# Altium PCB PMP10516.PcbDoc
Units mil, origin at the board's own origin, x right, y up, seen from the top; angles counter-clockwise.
Board outline 2300 x 2845 mil, 4 copper layers (Top Layer, MidLayer1, MidLayer2, Bottom Layer), stack 88.6 mil thick; 62 components, 21 nets, 113 pads, 13 vias.
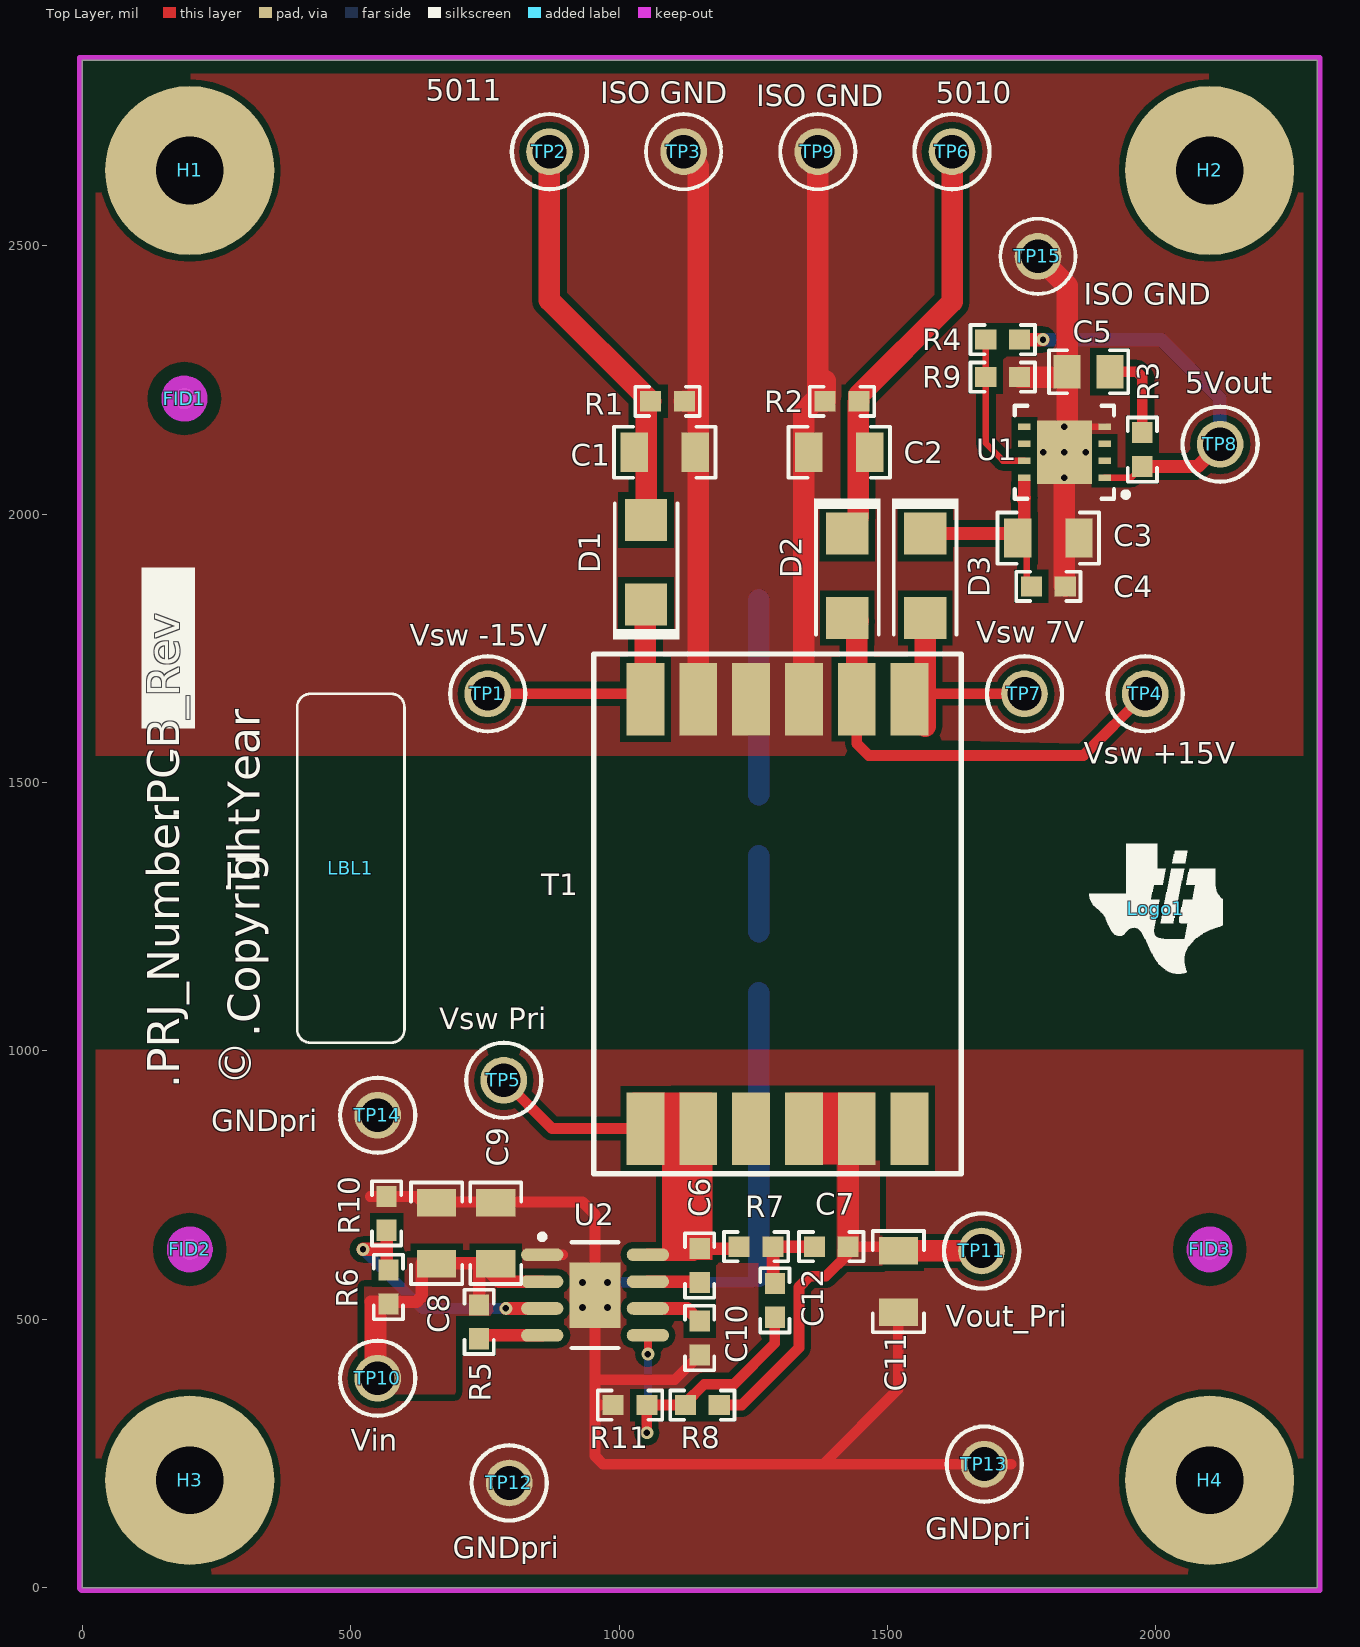
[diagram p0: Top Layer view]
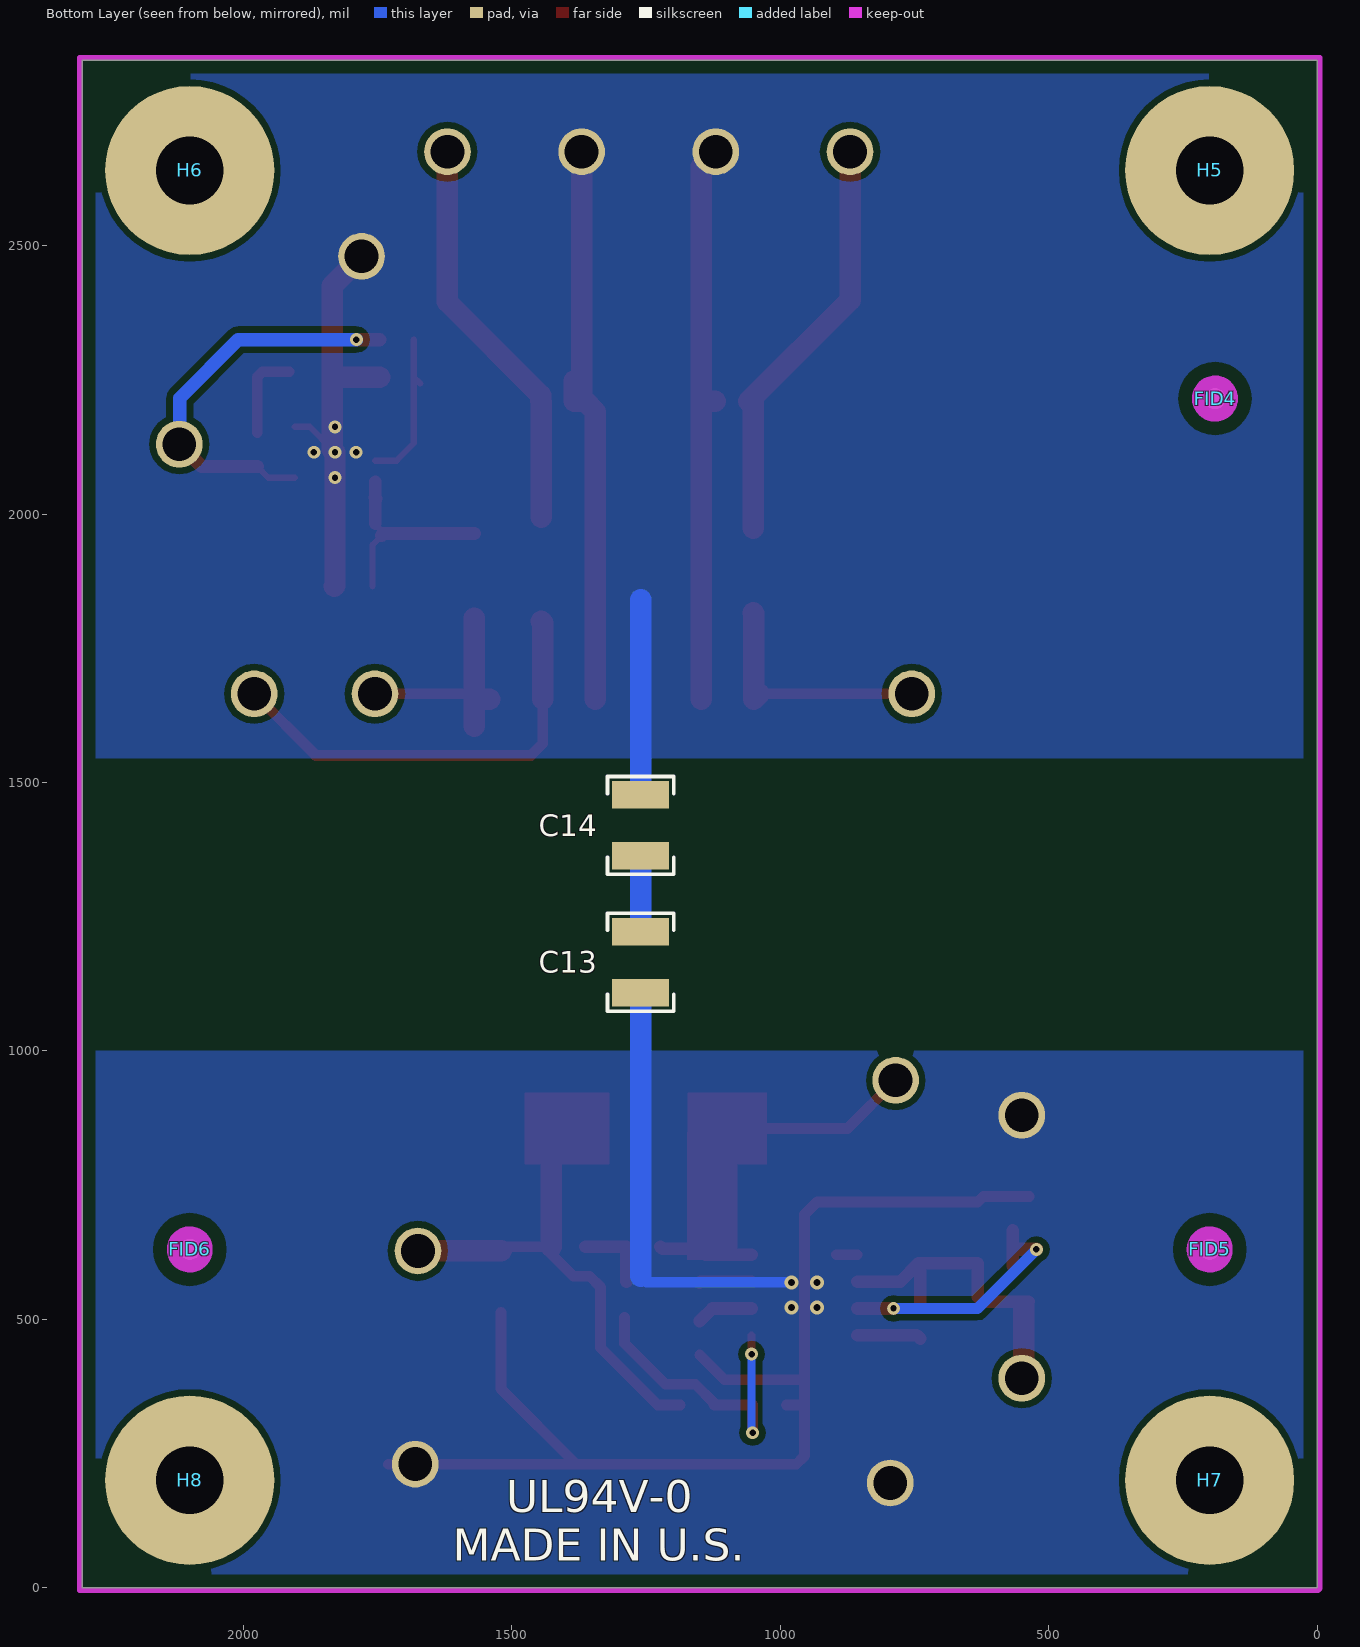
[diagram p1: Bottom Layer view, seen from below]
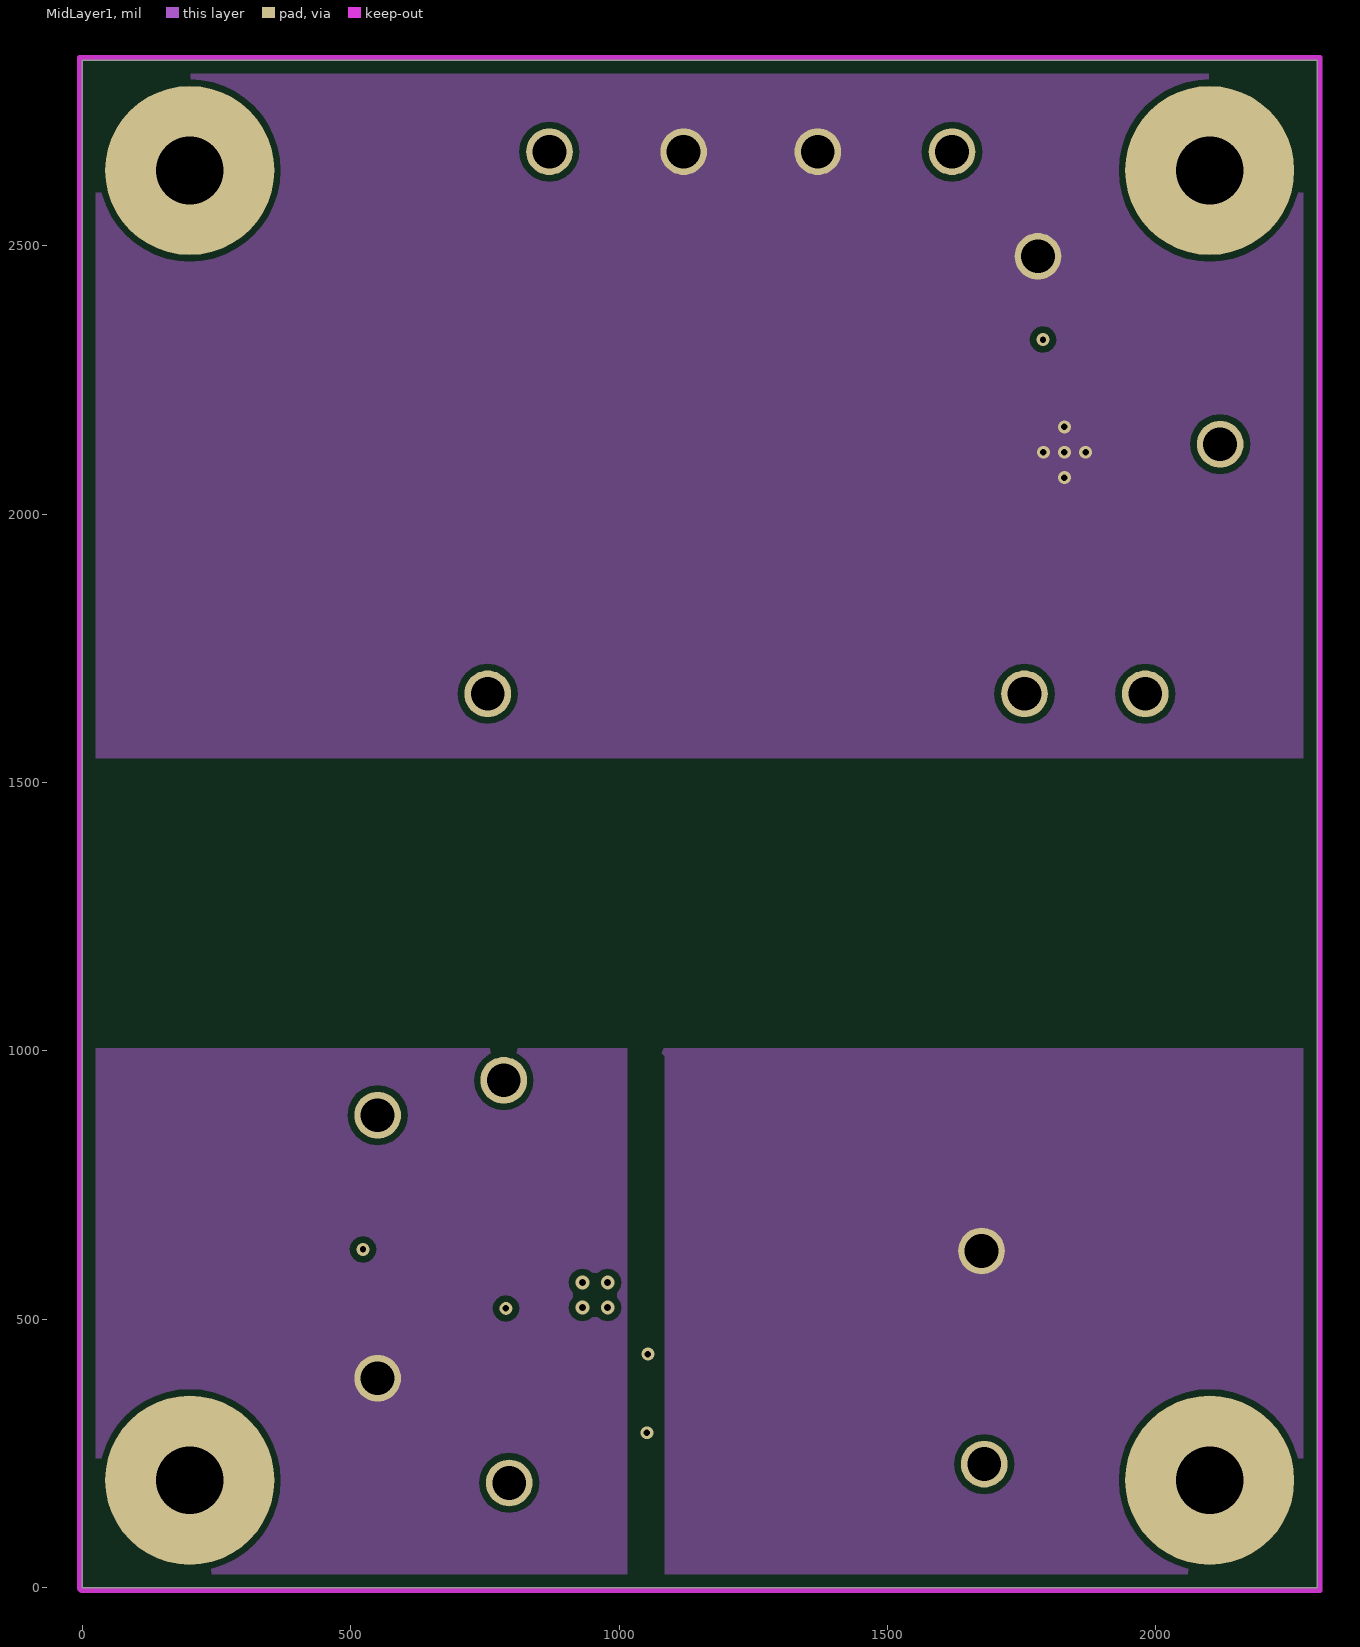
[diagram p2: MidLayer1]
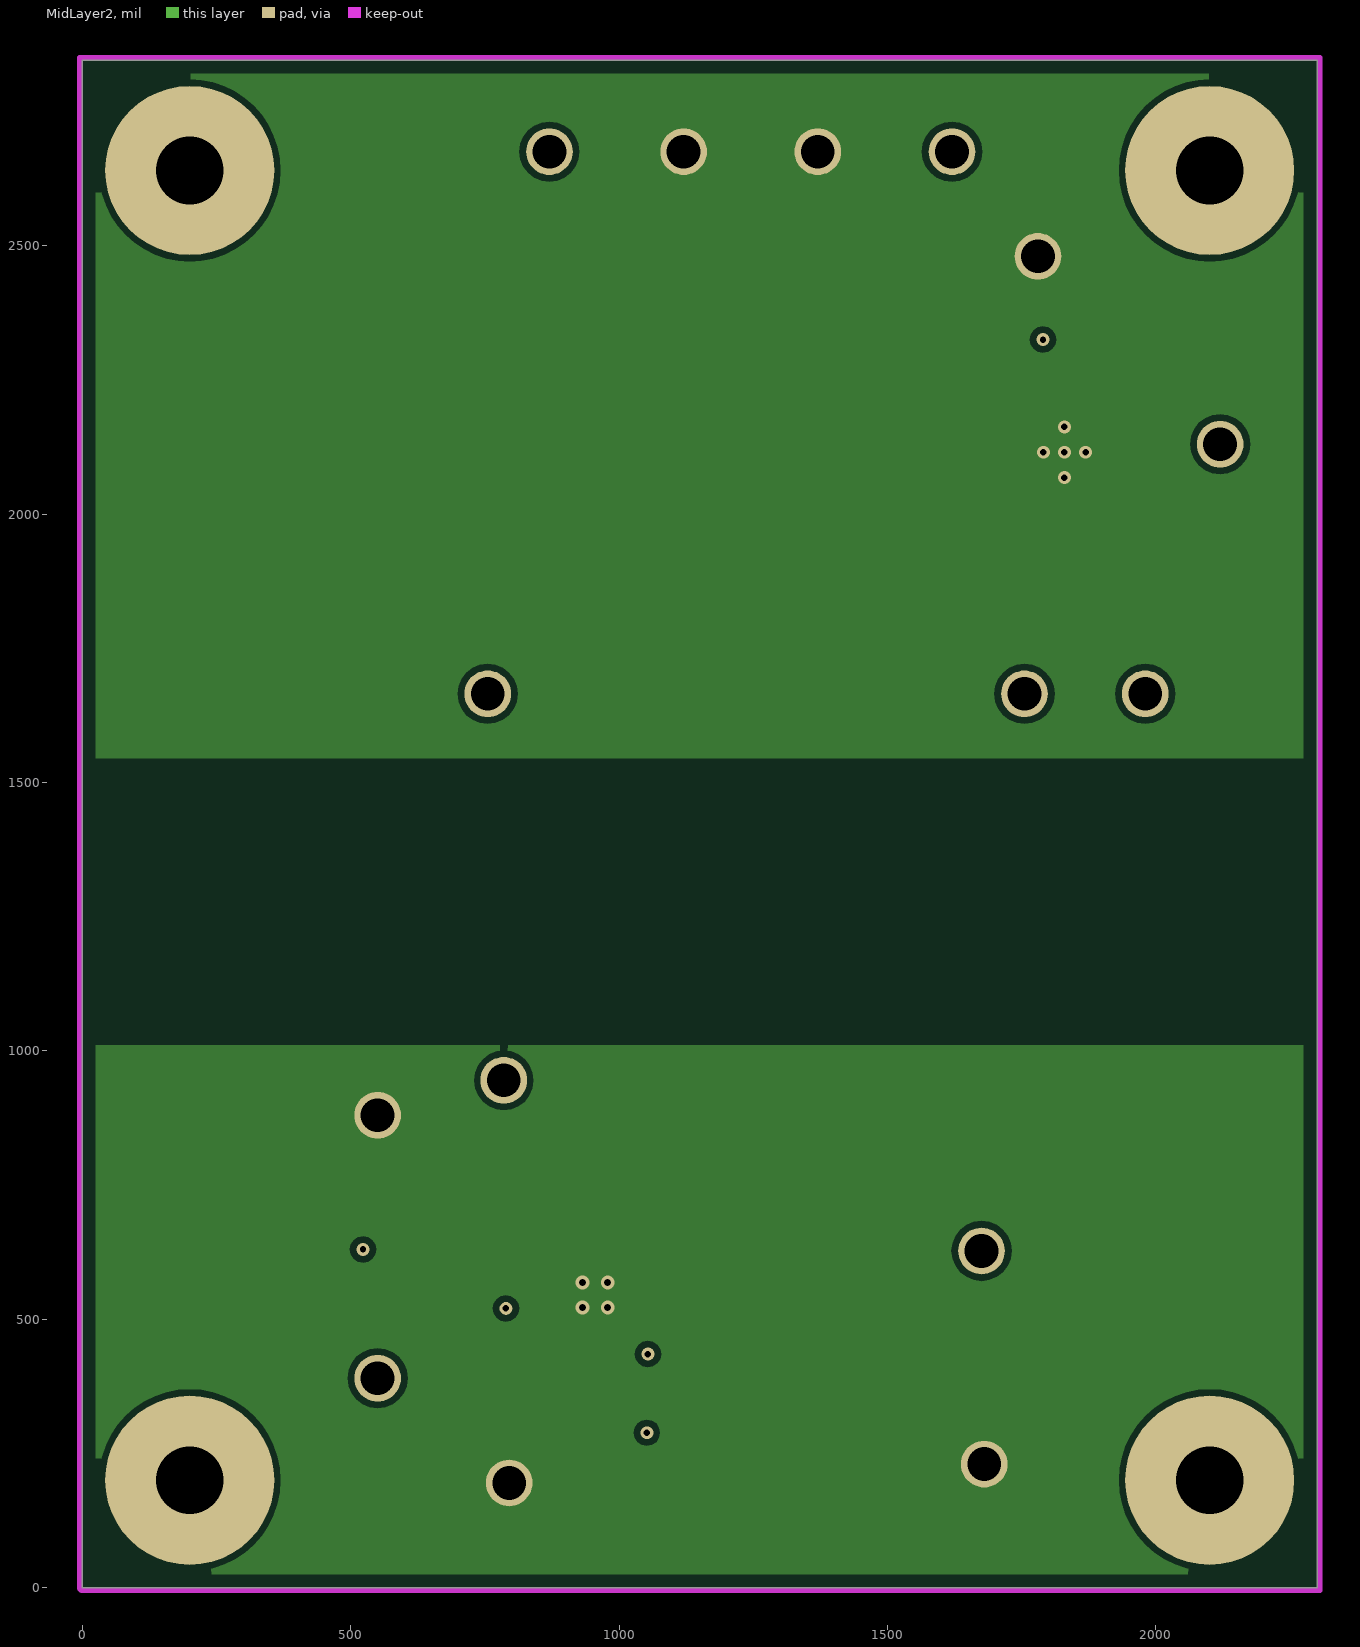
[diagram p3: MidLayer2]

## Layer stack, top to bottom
Top Solder: solder mask 0.4, Solder Resist, Dk 3.5
Top Layer: signal copper 1.4
Dielectric1: core 59.2, FR-4, Dk 4.8
MidLayer1: signal copper 0.7
Dielectric2: prepreg 12.6, FR-4, Dk 4.8
MidLayer2: signal copper 0.7
Dielectric3: core 12.6, FR-4, Dk 4.8
Bottom Layer: signal copper 1.4
Bottom Solder: solder mask 0.4, Solder Resist, Dk 3.5

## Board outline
0,0 0,2845 2300,2845 2300,0

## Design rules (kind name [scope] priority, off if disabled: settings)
AcuteAngle [All] p1: minimum=4.50000000000000E+0001 checktracksonly=FALSE
AssemblyTestPointUsage [All] p1: valid=2
Clearance Clearance_BoardEdge_MountingHoles [OnCopper and InComponentClass('Mounting Holes') vs IsKeepOut] p1: gap=40
Clearance Clearance_BoardEdge_Poly [OnCopper and InPoly vs IsKeepOut] p2: gap=25
Clearance Clearance_BoardEdge [OnCopper and Not InComponentClass('Logo') and not InComponentClass('FiducialMark') and not InRegion(1000,500,4000,800) and Not IsKeepout vs IsKeepOut] p3: gap=75
Clearance Clearance_Poly [InPolygon] p4: gap=12
Clearance [All] p5: gap=10
ComponentClearance ComponentClearance_Shunt [InComponentClass('Header') vs InComponentClass('Shunt')] p1: gap=0 collisioncheckmode=3 verticalgap=0 showdistances=FALSE
ComponentClearance ComponentClearance_Logo [InComponentClass('Logo')] p2: gap=50 collisioncheckmode=3 verticalgap=10 showdistances=FALSE
ComponentClearance ComponentClearance_ScrewToNut [(HasFootprint('NY PMS 440 0025 PH')) vs (HasFootprint('Keystone_1902C'))] p3: gap=5 collisioncheckmode=3 verticalgap=10 showdistances=FALSE
ComponentClearance ComponentClearance_MountingHoles [InComponentClass('Mounting Holes')] p4: gap=250 collisioncheckmode=3 verticalgap=100000 showdistances=FALSE
ComponentClearance ComponentClearance_SmallPassives [HasFootprint('0201*') or HasFootprint('0402*') or HasFootprint('0508') or HasFootprint('0603*') or HasFootprint('0612') or HasFootprint('0805*') or HasFootprint('0815*') or HasFootprint('0830*') or HasFootprint('1206*') or HasFootprint('1210*') or HasFootprint('1808*') or HasFootprint('1812*') or HasFootprint('1825*') or HasFootprint('2010*') or HasFootprint('2220*') or HasFootprint('2225*') or HasFootprint('2512*') or HasFootprint('2728*') or HasFootprint('3518*') vs HasFootprint('0201*') or HasFootprint('0402*') or HasFootprint('0508') or HasFootprint('0603*') or HasFootprint('0612') or HasFootprint('0805*') or HasFootprint('0815*') or HasFootprint('0830*') or HasFootprint('1206*') or HasFootprint('1210*') or HasFootprint('1808*') or HasFootprint('1812*') or HasFootprint('1825*') or HasFootprint('2010*') or HasFootprint('2220*') or HasFootprint('2225*') or HasFootprint('2512*') or HasFootprint('2728*') or HasFootprint('3518*')] p5: gap=20 collisioncheckmode=3 verticalgap=10 showdistances=FALSE
ComponentClearance ComponentClearance_THtoSMT [IsThruComponent vs IsSMTComponent] p6: gap=50 collisioncheckmode=3 verticalgap=30 showdistances=FALSE
ComponentClearance ComponentClearance_THtoTH [IsThruComponent vs IsThruComponent] p7: gap=118.11 collisioncheckmode=3 verticalgap=30 showdistances=FALSE
ComponentClearance [All] p8: gap=40 collisioncheckmode=3 verticalgap=10 showdistances=FALSE
DiffPairsRouting [All] p1: maxlimit=100 minlimit=10 mostfreqgap=10 toplayer_minwidth=15 toplayer_maxwidth=15 toplayer_prefwidth=15 midlayer1_minwidth=15 midlayer1_maxwidth=15 midlayer1_prefwidth=15 midlayer2_minwidth=15 midlayer2_maxwidth=15 midlayer2_prefwidth=15 bottomlayer_minwidth=15 bottomlayer_maxwidth=15 bottomlayer_prefwidth=15 maxuncoupledlength=1000
FabricationTestPointUsage TestPointUsage [All] p1: valid=2 allowmultiple=FALSE
FabricationTestpoint Testpoint [All] p1: side=3 testpointundercomponent=TRUE minsize=40 maxsize=100 preferedsize=60 minholesize=0 maxholesize=40 preferedholesize=32 testpointgrid=1 allowsidetop=TRUE allowsidebottom=TRUE usegrid=TRUE gridtolerance=0.01
FanoutControl Fanout_LCC [IsLCC] p1: bgadir=Out bgaviamode=Centered fanoutstyle=Auto fanoutdirection=Alternating viagrid=1 // Fanout_LCC (Default Rule)
FanoutControl Fanout_BGA [IsBGA] p2: bgadir=Out bgaviamode=Centered fanoutstyle=Auto fanoutdirection=Alternating viagrid=1 // Fanout_BGA (Default Rule)
FanoutControl Fanout_Default [All] p4: bgadir=Out bgaviamode=Centered fanoutstyle=Auto fanoutdirection=Alternating viagrid=1 // Fanout_Default (Default Rule)
FanoutControl Fanout_Small [(CompPinCount < 5)] p5: bgadir=Out bgaviamode=Centered fanoutstyle=Auto fanoutdirection=OutThenIn viagrid=1 // Fanout_Small (Default Rule)
HoleSize [All] p1: absolutevalues=TRUE maxlimit=251 minlimit=10 maxpercent=80.000 minpercent=20.000
MinimumAnnularRing MinimumAnnularRing_ThermalPadVias [IsVia and InAnyComponent] p1: minimumring=6
MinimumAnnularRing [All] p2: minimumring=6
MinimumSolderMaskSliver MinimumSolderMaskSliver_Logo [InComponentClass('Logo') vs InComponentClass('Logo')] p1: minsoldermaskwidth=0.7
MinimumSolderMaskSliver [All] p2: minsoldermaskwidth=3.94
PlaneConnect [All] p1: planeconnectstyle=Relief reliefexpansion=10 reliefentries=4 reliefconductorwidth=10 reliefairgap=10
PolygonConnect [All] p1: connectstyle=Direct reliefconductorwidth=10 reliefentries=4 polygonreliefangle="90 Angle" airgapwidth=10
RoutingVias ThermalPadVias [IsVia and InAnyComponent] p1: holewidth=12 width=24 viastyle="Through Hole" minholewidth=10 minwidth=22 maxholewidth=15 maxwidth=30
RoutingVias [All] p2: holewidth=16 width=34 viastyle="Through Hole" minholewidth=10 minwidth=22 maxholewidth=40 maxwidth=65
SMDToCorner [All] p1: distance=30000
SilkToSilkClearance [All] p1: silktosilkclearance=5
SilkToSolderMaskClearance SilkscreenOverComponentPads [IsPad] p1: minsilkscreentomaskgap=5 clearancetoexposedcopper=TRUE
SolderMaskExpansion [All] p1: expansion=1.97
UnpouredPolygon [All] p1: allowunpoured=FALSE
Width [All] p1: maxlimit=100 minlimit=6 preferedwidth=10 checkconnectedcopper=TRUE
15 further rules are at their usual default settings.

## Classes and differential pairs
component class PMP10516_Rev2: C1 C2 C3 C4 C5 C6 C7 C8 C9 C10 C11 C12 C13 C14 D1 D2 D3 R1 R2 R3 R4 R5 R6 R7 R8 R9 R10 R11 T1 TP1 TP2 TP3 TP4 TP5 TP6 TP7 TP8 TP9 TP10 TP11 TP12 TP13 TP14 TP15 U1 U2
component class Label: LBL1
component class FiducialMark: FID1 FID2 FID3 FID4 FID5 FID6
component class PMP10516_Hardware_ANSI-B: FID1 FID2 FID3 FID4 FID5 FID6 H1 H2 H3 H4 H5 H6 H7 H8 LBL1 Logo1
component class Logo: Logo1
component class "Mounting Holes": H1 H2 H3 H4

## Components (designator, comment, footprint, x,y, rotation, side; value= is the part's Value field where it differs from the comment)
C1 "GRM31CR71E106KA12L" 1206 1085,2115 r180 top
C2 "GRM31CR71E106KA12L" 1206 1410,2115 r180 top
C3 "GRM31CR71E106KA12L" 1206 1799.45,1955 r0 top
C4 "06033C104JAT2A" 0603 1799.45,1865 r0 top
C5 "C0805C225K8RACTU" 0805_HV 1874.45,2265 r180 top
C6 "06035C104KAT2A" 0603 1150,600 r270 top
C7 "C0603C223K5RACTU" 0603 1395,635 r180 top
C8 "GRM31CR71H225KA88L" 1206 660,660 r90 top
C9 "GRM31CR71H225KA88L" 1206 770,660 r90 top
C10 "GRM188R71E105KA12D" 0603 1150,465 r270 top
C11 "GRM31CR71E106KA12L" 1206 1520,570 r270 top
C12 "C0603C102J5GAC" 0603 1290,535 r270 top
C13 "VJ1210A222JXGAT5Z" 1210 1260,1165 r270 bottom
C14 "VJ1210A222JXGAT5Z" 1210 1260,1420 r270 bottom
D1 "ES1D-13-F" SMA 1050,1910 r90 top
D2 "ES1D-13-F" SMA 1425,1885 r270 top
D3 "ES1D-13-F" SMA 1570,1885 r270 top
FID1 "Fiducial" Fiducial10-20#1 190,2215 r0 top
FID2 "Fiducial" Fiducial10-20#1 200,630 r0 top
FID3 "Fiducial" Fiducial10-20#1 2100,630 r0 top
FID4 "Fiducial" Fiducial10-20#2 190,2215 r180 bottom
FID5 "Fiducial" Fiducial10-20#2 200,630 r180 bottom
FID6 "Fiducial" Fiducial10-20#2 2100,630 r180 bottom
H1 "NY PMS 440 0025 PH" "NY PMS 440 0025 PH" 200,2640 r0 top locked
H2 "NY PMS 440 0025 PH" "NY PMS 440 0025 PH" 2100,2640 r0 top locked
H3 "NY PMS 440 0025 PH" "NY PMS 440 0025 PH" 200,200 r0 top locked
H4 "NY PMS 440 0025 PH" "NY PMS 440 0025 PH" 2100,200 r0 top locked
H5 "1902C" Keystone_1902C 200,2640 r180 bottom locked
H6 "1902C" Keystone_1902C 2100,2640 r180 bottom locked
H7 "1902C" Keystone_1902C 200,200 r180 bottom locked
H8 "1902C" Keystone_1902C 2100,200 r180 bottom locked
LBL1 "Size: 0.65\" x 0.20 \"" Label_650x200 500,1340 r90 top
Logo1 "Texas Instruments" TI_Symbol_Overlay_Medium 2000,1265 r0 top
R1 "Used in BOM report" 0603 1090,2210 r0 top
R2 "Used in BOM report" 0603 1415,2210 r0 top
R3 "CRCW06030000Z0EA" 0603 1974.45,2120 r270 top
R4 "CRCW060331K6FKEA" 0603 1714.45,2325 r0 top
R5 "CRCW0603365KFKEA" 0603 739,495 r270 top
R6 "CRCW0603100KFKEA" 0603 570,560 r270 top
R7 "CRCW060310K0FKEA" 0603 1255,635 r0 top
R8 "CRCW0603143KFKEA" 0603 1155,340 r0 top
R9 "CRCW060310K0FKEA" 0603 1714.45,2255 r180 top
R10 "CRCW06036K98FKEA" 0603 566.7,697.19 r270 top
R11 "CRCW060320K0FKEA" 0603 1020,340 r0 top
T1 "RA7157-AL" RA7157-AL 1295,1255 r90 top
TP1 "Vsw -15V" Keystone5012 755,1665 r0 top
TP2 "5011" Keystone5011 870,2675 r0 top
TP3 "ISO GND" Keystone5126 1120,2675 r0 top
TP4 "Vsw +15V" Keystone5012 1980,1665 r0 top
TP5 "Vsw Pri" Keystone5012 785,945 r0 top
TP6 "5010" Keystone5010 1620,2675 r0 top
TP7 "Vsw 7V" Keystone5012 1755,1665 r0 top
TP8 "5Vout" Keystone5010 2119.45,2130 r0 top
TP9 "ISO GND" Keystone5126 1370,2675 r180 top
TP10 "Vin" Keystone5010 550,390 r0 top
TP11 "Vout_Pri" Keystone5010 1675,627.09 r0 top
TP12 "GNDpri" Keystone5011 795,195 r0 top
TP13 "GNDpri" Keystone5011 1680,230 r0 top
TP14 "GNDpri" Keystone5011 550,880 r0 top
TP15 "ISO GND" Keystone5126 1780,2480 r0 top
U1 "LP2951CSD" SDC08A 1829.45,2115 r180 top
U2 "LM5017MRE/NOPB" DDA0008B_N 955,545 r0 top

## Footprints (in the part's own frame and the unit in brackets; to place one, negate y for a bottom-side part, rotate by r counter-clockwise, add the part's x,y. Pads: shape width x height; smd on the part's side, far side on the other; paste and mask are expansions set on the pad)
0603 [mm] "0603 from SM-752 data"
  rect 1x0.95 smd: 1(-0.8,0) 2(0.8,0)
  silkscreen extent -1.52,-0.69 1.52,0.69, body extent -0.87,-0.47 0.87,0.47, height 0.85
0805_HV [mil] "0805 with 30mil clearance between pads"
  rect 50x63 smd: 1(-40,0) 2(40,0)
  silkscreen extent -74,-40 74,40, body extent -43,-29 43,29, height 43
1206 [mm] "1206 from SM-752 data"
  rect 1.3x1.85 smd: 1(-1.45,0) 2(1.45,0)
  silkscreen extent -2.4,-1.21 2.4,1.21, body extent -1.7,-0.9 1.7,0.9, height 1.35
1210 [mm] "1210 from SM-752 data"
  rect 1.3x2.7 smd: 1(-1.45,0) 2(1.45,0)
  silkscreen extent -2.32,-1.57 2.32,1.57, body extent -1.7,-1.35 1.7,1.35, height 1.35
DDA0008B_N [mm] "SOIC, 8-Leads, Body 4.9x3.9mm, Pitch 1.27mm, Exposed Pad, IPC Medium Density"
  oval 2x0.6 smd: 1(-2.5,1.905) 2(-2.5,0.635) 3(-2.5,-0.635) 4(-2.5,-1.905) 5(2.5,-1.905) 6(2.5,-0.635) 7(2.5,0.635) 8(2.5,1.905)
  rect 2.41x3.1 smd: 9(0,0)
  silkscreen extent -2.62,-2.5 1.1,2.88, body extent -2,-2.5 2,2.5, height 1.68
Fiducial10-20#1 [mm]
  round 1 smd paste-0.5 mask+0.5: 1(0,0)
  Top Layer keep-out circle w1.178: c0,0 r0.5
Fiducial10-20#2 [mm]
  round 1 smd mask+0.5: 1(0,0)
  Top Layer keep-out circle w1.178: c0,0 r0.5
Keystone5010 [mil] "Keystone Multipurpose loops"
  round 87 hole 63: 1(0,0)
  silkscreen extent -70,-70 70,70, body extent -63,-63 63,62, height 319
Keystone5011 [mil] "Keystone Multipurpose loops"
  round 87 hole 63: 1(0,0)
  silkscreen extent -70,-70 70,70, body extent -63,-63 63,62, height 319
Keystone5012 [mil] "Keystone Multipurpose loops"
  round 87 hole 63: 1(0,0)
  silkscreen extent -70,-70 70,70, body extent -63,-63 63,62, height 319
Keystone5126 [mil] "Keystone Multipurpose loops"
  round 87 hole 63: 1(0,0)
  silkscreen extent -70,-70 70,70, body extent -63,-63 63,62, height 319
Keystone_1902C [mil] "Hex Standoff, 4-40 threaded, nylon"
  body extent -145,-126 146,126, height 501
Label_650x200 [mil] "Thermal Transfer Label"
  silkscreen extent -325,-100 325,100, body extent -326,-101 326,101, height 1
"NY PMS 440 0025 PH" [mm] "4-40 nylon screw and mounting hole"
  round 8 hole 3.2: 1(0,0)
  body extent -3.3,-3.3 3.3,3.3, height 2.69
RA7157-AL [mm] "COILCRAFT RA7157-AL CUSTOM TRANSFORMER"
  round 1.524 on Top Overlay: 0(-6.9,6.2)
  rect 3.43x1.79 smd: 1(-10.155,6.25) 2(-10.155,3.75) 3(-10.155,1.25) 4(-10.155,-1.25) 5(-10.155,-3.75) 6(-10.155,-6.25) 7(10.155,-6.25) 8(10.155,-3.75) 9(10.155,-1.25) 10(10.155,1.25) 11(10.155,3.75) 12(10.155,6.25)
  silkscreen extent -12.3,-8.7 12.3,8.7, body extent -12.3,-8.7 12.3,8.7, height 8.65
SDC08A [mm] "SON, 8-Leads, Body 4x4mm, Pitch 0.8mm, NSC Recommended"
  rect 0.6x0.3 smd paste-0.15 mask+0.051: 1(-1.9,1.2) 2(-1.9,0.4) 3(-1.9,-0.4) 4(-1.9,-1.2) 5(1.9,-1.2) 6(1.9,-0.4) 7(1.9,0.4) 8(1.9,1.2)
  rect 2.6x3 smd paste-1.5 mask+0.051: 9(0,0)
  silkscreen extent -3.03,-2.2 2.35,2.2, body extent -2.05,-2.05 2.05,2.05, height 0.8
SMA [mm] "Molded Diode, 2-Leads, Body 4.3x2.6mm, IPC Medium Density, based on OnSemi component dimensions and land pattern"
  rect 2x2 smd: 1(-2,0) 2(2,0)
  silkscreen extent -3.66,-1.57 2.79,1.57, body extent -2.6,-1.3 2.6,1.3, height 2.42
TI_Symbol_Overlay_Medium [mil]
  silkscreen extent -124,-122 124,120

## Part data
C1 C2 C3 C11: "CAP, CERM, 10uF, 25V, +/-10%, X7R, 1206"
C4: "CAP, CERM, 0.1uF, 25V, +/-5%, X7R, 0603"
C5: "CAP, CERM, 2.2uF, 10V, +/-10%, X7R, 0805"
C6: "CAP, CERM, 0.1uF, 50V, +/-10%, X7R, 0603"
C7: "CAP, CERM, 0.022uF, 50V, +/-10%, X7R, 0603"
C8 C9: "CAP, CERM, 2.2uF, 50V, +/-10%, X7R, 1206"
C10: "CAP, CERM, 1uF, 25V, +/-10%, X7R, 0603"
C12: "CAP, CERM, 1000pF, 50V, +/-5%, C0G/NP0, 0603"
C13 C14: "CAP, CERM, 2200 pF, 1000 V, +/- 5%, C0G/NP0, 1210"
D1 D2 D3: "Diode, Ultrafast, 200V, 1A, SMA"
FID1 FID2 FID3 FID4 FID5 FID6: "Fiducial mark.  There is nothing to buy or mount."
H1 H2 H3 H4: "Machine Screw, Round, #4-40 x 1/4, Nylon, Philips panhead"
H5 H6 H7 H8: "Standoff, Hex, 0.5\"L #4-40 Nylon"
LBL1: library part THT-14-423-10, "Thermal Transfer Printable Labels, 0.650\" W x 0.200\" H - 10,000 per roll"
Logo1: library part TI_Logo, "Texas Instrument Corporate Signature"
R1 R2: library part Resistor, "RES, xxx ohm, x%, xW, [PackageReference]"
R3: "RES, 0 ohm, 5%, 0.1W, 0603"
R4: "RES, 31.6k ohm, 1%, 0.1W, 0603"
R5: "RES, 365k ohm, 1%, 0.1W, 0603"
R6: "RES, 100k ohm, 1%, 0.1W, 0603"
R7 R9: "RES, 10.0k ohm, 1%, 0.1W, 0603"
R8: "RES, 143k ohm, 1%, 0.1W, 0603"
R10: "RES, 6.98k ohm, 1%, 0.1W, 0603"
R11: "RES, 20.0k ohm, 1%, 0.1W, 0603"
T1: library part RA7157-AL_V2, "1:1.5:1.5:0.7 Turns Ratio Transformer"
TP1 TP4 TP5 TP7: library part 5012, "Test Point, Multipurpose, White, TH"
TP2: "Test Point, Multipurpose, Black, TH"
TP3 TP9 TP15: library part 5126, "Test Point, Multipurpose, Green, TH"
TP6: "Test Point, Multipurpose, Red, TH"
TP8 TP10 TP11: library part 5010, "Test Point, Multipurpose, Red, TH"
TP12 TP13 TP14: library part 5011, "Test Point, Multipurpose, Black, TH"
U1: "Series of Adjustable Micropower Voltage Regulators, 8-pin LLP"
U2: "100V, 600mA Constant On-Time Synchronous Buck Regulator, DDA0008B"

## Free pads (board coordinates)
  round 24 hole 12: 0(789,520)

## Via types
v1: diameter 24, hole 12, Top Layer to Bottom Layer, 9 vias
v2: diameter 25.98, hole 12.99, Top Layer to Bottom Layer, tented top, 4 vias

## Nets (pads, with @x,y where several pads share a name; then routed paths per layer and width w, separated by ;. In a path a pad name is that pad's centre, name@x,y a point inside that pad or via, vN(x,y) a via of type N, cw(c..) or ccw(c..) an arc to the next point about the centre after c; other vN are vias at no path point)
5VOUT: R3.2 R4.2 TP8.1 U1.1 | length 745
  Top Layer w11.81: U1.1 1953.7,2067.76 R3.2
  Top Layer w25: R4.2 v1(1789.45,2325) ; R3.2 2077.95,2088.5 TP8.1
  Bottom Layer w25: v1(1789.45,2325) 2009.45,2325 2118.94,2215.51 TP8.1@2118.94,2129.87
"7V SW": D3.2 T1.7 TP7.1 | length 405
  Top Layer w20: 1580.2,1665 TP7.1
  Top Layer w40: T1.7 T1.7@1570,1654.8 ; T1.7@1570,1605 T1.7@1570,1654.8 ; D3.2 T1.7@1570,1654.8
"+15V SW": D2.2 T1.8 TP4.1 | length 822.9
  Top Layer w20: T1.8 1442.64,1572.36 1465,1550 1865,1550 TP4.1
  Top Layer w40: T1.8 1442.64,1797.64 D2.2@1445,1800
+15VOUT: C2.1 D2.1 R2.2 TP6.1 | length 753.7
  Top Layer w40: D2.1@1445,1993.74 1445,2208.5 R2.2 1446.5,2221.5 1620,2395 TP6.1
"-15V SW": D1.1 T1.12 TP1.1 | length 460.1
  Top Layer w20: TP1.1 T1.12@1038.74,1665
  Top Layer w40: T1.12@1038.74,1665 T1.12 1048.94,1815.2 D1.1@1050,1816.26
-15VOUT: C1.2 D1.2 R1.1 TP2.1 | length 786.4
  Top Layer w40: TP2.1 870,2398.5 R1.1 R1.1@1050,2201.5 ; D1.2@1050,1973.74 D1.2 R1.1@1050,2201.5 ; R1.1@1050,2205 R1.1@1050,2201.5
BST: C6.2 U2.7 | length 97.2
  Top Layer w23.62: U2.7 1148.5,570 C6.2
FB: C12.2 R8.1 R11.2 U2.5 | length 570.6
  Top Layer w15: v1(1053.43,435) U2.5
  Top Layer w20: v1(1051.5,288.5) R11.2 R8.1 1123.5,343.68 1158.53,378.7 1213.7,378.7 1290,455 C12.2
  Bottom Layer w15: v1(1051.5,288.5) 1053.42,290.43 v1(1053.43,435)
GND: C8.2 C9.2 C10.2 C11.2 C13.2 R10.1 R11.1 TP12.1 TP13.1 TP14.1 U2.1 U2.9 | length 3100.1
  Top Layer w20: 536,728.5 621.83,728.5 632,718.33 931.67,718.33 955,695 U2.9@955,565 ; U2.1 U2.1@895,620 ; U2.9@955,560 U2.9 955,387.19 ; R11.1 955,340 ; C10.2 1103.68,387.19 955,387.19 ; C11.2 1520,370 1380,230 ; 1730,230 TP13.1 1380,230 ; 955,340 955,387.19 ; 955,340 955,245 970,230 1380,230
  Bottom Layer w20: v2(978.62,568.62) 1248.62,568.62 1260,580
  Bottom Layer w40: 1260,580 C13.2
  other v2: 931.38,521.38 978.62,521.38 931.38,568.62
"ISO GND": C1.1 C2.2 C3.2 C4.2 C5.2 C14.1 R1.2 R2.1 R9.1 T1.9 T1.10 T1.11 TP3.1 TP9.1 TP15.1 U1.4 U1.9 | length 3277.5
  Top Layer w11.81: v1(1829.45,2115) 1834.45,2120 1876.69,2162.24 U1.4
  Top Layer w40: R1.2 1147.36,2210 ; T1.11 1147.36,2210 ; TP3.1@1147.36,2647.64 1147.36,2210 ; T1.9 1344.21,2190.79 1363.43,2210 ; TP9.1 1370,2216.57 1363.43,2210 ; 1383.5,2248.5 R2.1 1363.43,2210 ; R9.1 C5.2@1824.45,2255 ; TP15.1@1779.5,2480.13 1834.45,2425.18 C5.2 U1.9@1834.45,2120 ; v1(1829.45,2115) v1(1829.45,2067.76) 1829.45,1866.5 C4.2
  Bottom Layer w40: C14.1 1260,1840
  other v1: 1790.08,2115 1868.82,2115 1829.45,2162.24
"LDO FB": R4.1 R9.2 U1.7 | length 296
  Top Layer w11.81: R9.2@1670.95,2242.99 R9.2 ; R4.1 R9.2 ; U1.7 1714.45,2099.25 1714.45,2100 1682.95,2131.5 R9.2
LDOIN: C3.1 C4.1 D3.1 U1.8 | length 373.1
  Top Layer w11.81: C3.1@1742.36,1960 1759.45,1942.91 C4.1@1759.45,1865 ; C3.1@1742.95,1970 C3.1@1754.65,1981.69
  Top Layer w23.62: C3.1@1754.65,1981.69 1754.65,2030.35 1754.65,2060
  Top Layer w25: D3.1 1738.62,1963.74 C3.1@1742.36,1960 ; 1753.03,2028.74 1754.65,2030.35
NetC5_1: C5.1 R3.1 | length 167.6
  Top Layer w20: C5.1 1964.45,2265 1974.45,2255 R3.1
NetC13_1: C13.1 C14.2 | length 140.8
  Bottom Layer w40: C13.1 C14.2
RIPPLEINJ: C7.2 C12.1 R7.2 | length 142
  Top Layer w23.62: C12.1@1286.5,570 R7.2 C7.2
RON: R5.2 U2.4 | length 120.3
  Top Layer w23.62: R5.2 745.5,470 U2.4
SWPRI: C6.1 R7.1 T1.1 T1.2 TP5.1 U2.8 | length 575.9
  Top Layer w20: TP5.1 874.8,855.2 T1.1
  Top Layer w23.62: U2.8 1138.5,620 C6.1 1220,631.5 R7.1
  Top Layer w40: T1.1 T1.2
UVLO: pad.0 R6.1 R10.2 U2.3 | length 490.9
  Top Layer w15: 562.72,630 566.7,626.02
  Top Layer w23.62: R6.1@566.7,599.8 566.7,626.02 R10.2 ; pad.0 U2.3
  Top Layer w25: v1(522.72,630) 562.72,630
  Bottom Layer w20: v1(522.72,630) 632.72,520 pad.0
VCC: C10.1 U2.6 | length 106.3
  Top Layer w23.62: U2.6 1126.5,520 C10.1
VIN: C8.1 C9.1 R5.1 R6.2 TP10.1 U2.2 | length 611.9
  Top Layer w23.62: 537,532.5 622.5,532.5 632,542 632,604.16 C9.1@742,604.16 ; R5.1 739,601.16 C9.1@742,604.16 ; U2.2 776.16,570 C9.1@742,604.16
  Top Layer w40: TP10.1@546.33,390 546.33,523.18
VOUTPRI: C7.1 C11.1 R8.2 T1.4 T1.5 TP11.1 | length 1013.5
  Top Layer w20: R8.2 1228.25,340 1335,446.75 1335,560 1355,580 1385,580 1426.5,621.5 C7.1 1512.09,635 C11.1
  Top Layer w40: T1.4 T1.5 1426.5,839.06 C7.1 ; C11.1 TP11.1
pads on no net: FID1.1 FID2.1 FID3.1 FID4.1 FID5.1 FID6.1 H1.1 H2.1 H3.1 H4.1 T1.0 T1.3 T1.6 U1.2 U1.3 U1.5 U1.6

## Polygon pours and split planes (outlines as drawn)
VOUTPRI on Top Layer "Top Layer-VOUTPRI" (solid, remove dead copper, pour order 8): 1405,795 1405,600 1490,600 1490,655 1485,655 1485,795
"ISO GND" on Top Layer "Top Layer-ISOGND" (solid, remove dead copper, pour order 13): 0,2845 2300,2845 2315,2830 2315,1550 10,1550 0,1560
GND on Top Layer "Top Layer-GND" (solid, remove dead copper, pour order 20): -8.93,-12.76 6.07,2.24 2306.07,2.24 2306.07,997.24 2301.07,1002.24 -3.5,1002.24
VIN on Top Layer "Top Layer-VIN" (solid, remove dead copper, pour order 11): 525,360 700,360 695.3,364.7 695.3,506.25 766.25,506.25 770,510 770,620 764,614 605,614 605,594.3 565.54,560 525,560
GND on Bottom Layer "Bottom Layer-GND" (solid, remove dead copper, pour order 22): -10,5 2300,5 2315,-10 2305,0 2305,1000 0,1000
"ISO GND" on Bottom Layer "Bottom Layer-ISOGND" (solid, remove dead copper, pour order 12): -5,2850 2305,2850 2300,1545 -5,1545
"ISO GND" on MidLayer1 "MidLayer1-ISO GND" (solid, remove dead copper, pour order 18): 0,2845 2300,2845 2305,2850 2300,2845 2300,1545 5,1545 0,1540
VOUTPRI on MidLayer1 "MidLayer1-VOUTPRI" (solid, remove dead copper, pour order 9): 2300,0 2300,1005 1070,1005 1065,1010 1085,990 1085,0
VIN on MidLayer1 "MidLayer1-VIN" (solid, remove dead copper, pour order 10): 0,0 1010,0 1015,5 1015,1005 0,1005 -5,1000
"ISO GND" on MidLayer2 "MidLayer2-ISO GND" (solid, remove dead copper, pour order 16): 0,2845 2300,2845 2300,1550 2305,1545 5,1545
GND on MidLayer2 "MidLayer2-GND" (solid, remove dead copper, pour order 24): 2315,1010 2315,0 0,0 0,1005 -5,1010

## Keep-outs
Keep-Out Layer:
  lines w10: -5,0 ccw(c0,0) 0,-5 ; -5,0 ccw(c0,0) 0,-5 ; -5,0 ccw(c0,0) 0,-5 ; -5,0 ccw(c0,0) 0,-5 ; -5,0 ccw(c0,0) 0,-5 ; -5,0 ccw(c0,0) 0,-5 ; -5,0 -5,2850 2305,2850 2305,-5 0,-5
  text ".Layer_Name" at 577,-858.49 h60

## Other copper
Top Layer:
  rectangle net SWPRI: 1025,788 1173,922
  rectangle net VOUTPRI: 1318,788 1476,922
  rectangle net SWPRI: 1080,610 1173.7,849.65
  text ".Layer_Name" at 577,-858.49 h60
Bottom Layer:
  text ".Layer_Name" at 577,-858.49 h60

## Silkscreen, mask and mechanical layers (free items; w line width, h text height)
Top Overlay:
  region: 110,1900 110,1600 210,1600 210,1900
  text "-" at 190,1535 h60 r90
  text ".PCB_Rev" at 180,1430 h60 r90
  text "TI" at 330,1301 h60 r90
  text ".CopyrightYear" at 330,1025 h60 r90
  text "©" at 335,935 h105 r90
  text ".PRJ_Number" at 180,930 h60 r90
  text ".Layer_Name" at 577,-858.49 h60
Bottom Overlay:
  text "UL94V-0" at 1510,140 h60
  text "MADE IN U.S." at 1610,50 h60
  text ".Layer_Name" at 577,-858.49 h60
Top Paste:
  text ".Layer_Name" at 577,-858.49 h60
Bottom Paste:
  text ".Layer_Name" at 577,-858.49 h60
Top Solder:
  text ".Layer_Name" at 577,-858.49 h60
  text ".Layer_Name" at 577,-858.49 h60
Bottom Solder:
  text ".Layer_Name" at 577,-858.49 h60
Drill Guide:
  text ".Layer_Name" at 577,-858.49 h60
M1 Board Outline:
  the board outline again, w10
  text ".Layer_Name" at 577,-858.49 h60
M2 Board Dimensions:
  rectangle: 124.5,-410.5 499.5,-285.5
  rectangle: -0.5,-285.5 124.5,-160.5
  lines w7: -0.5,-285.5 999.5,-285.5 ; 124.5,-410.5 124.5,-160.5 ; 249.5,-410.5 249.5,-160.5 ; 499.5,-410.5 499.5,-160.5 ; 749.5,-410.5 749.5,-160.5 ; -0.5,-410.5 -0.5,-160.5 999.5,-160.5 999.5,-410.5 -0.5,-410.5
  lines w10: -0.5,-475.5 -0.5,-455.5 ; 59.5,-485.5 -0.5,-465.5 ; 59.5,-445.5 -0.5,-465.5 ; 223.58,-465.5 -0.5,-465.5 ; 775.42,-465.5 999.5,-465.5 ; 939.5,-485.5 999.5,-465.5 ; 939.5,-445.5 999.5,-465.5 ; 999.5,-475.5 999.5,-455.5
  text "1000 (mil)" at 233.58,-501.49 h60
  text ".Layer_Name" at 577,-858.49 h60
M3 3D STEP Top:
  text ".Layer_Name" at 577,-858.49 h60
M4 3D STEP Bottom:
  text ".Layer_Name" at 577,-858.49 h60
M5 Assembly Top:
  lines w10: -292,-930.17 6308,-930.17 ; -292,-726.83 6310,-726.83 ; -292,-523.5 -292,-1133.5 3713,-1133.5 6310,-1133.5 6310,-523.5 -291.5,-523.5 -291.5,-1133.5 1284,-1133.5 ; 2173,-1133.5 2173,-523.5 ; 3440,-726.83 3440,-523.5 ; 4280,-726.83 4280,-523.5 ; 4902,-1140 4902,-937.17
  text "COMPONENTS MARKED 'DNP' SHOULD NOT BE POPULATED." at 1153.5,-318.5 h60
  text "ASSEMBLY VARIANT:" at 1153,-434 h60
  text ".VariantName" at 2189,-434 h60
  text "PCB VIEWED FROM TOP SIDE" at -228.5,-655.67 h60
  text "BOARD #:" at 2248,-655.67 h60
  text ".PRJ_Number" at 2793.5,-655.67 h60
  text "REV:" at 3638,-655.67 h60
  text ".PCB_Rev" at 3929.5,-655.67 h60
  text "SVN REV:" at 4476,-655.67 h60
  text ".VersionControl_RevNumber" at 4982,-655.67 h60
  text "IGNORE ->" at -228.5,-858.49 h60
  text "PLOT NAME =" at -228.5,-1064.34 h60
  text ".plot_File_Name" at 577,-1064.34 h60
  text "GENERATED    :" at 2250,-1064.34 h60
  text ".Print_Date" at 3119.5,-1064.34 h60
  text ".Print_Time" at 3848.5,-1064.34 h60
  text "TEXAS INSTRUMENTS" at 5113,-1064.34 h60
M6 Assembly Bottom:
  lines w10: -292.5,-727.33 6309.5,-727.33 ; -290.5,-930.67 6309.5,-930.67 ; 1115.5,-1140.5 1115.5,-937.67 ; 1737.5,-727.33 1737.5,-524 ; 2577.5,-727.33 2577.5,-524 ; 3844.5,-1134 3844.5,-524 ; 4733.5,-1134 6309,-1134 6309,-524 -292.5,-524 -292.5,-1134 2304.5,-1134 6309.5,-1134 6309.5,-524
  text "COMPONENTS MARKED 'DNP' SHOULD NOT BE POPULATED." at 6102,-318 h60
  text ".VariantName" at 5058,-434 h60
  text "ASSEMBLY VARIANT:" at 6097,-434 h60
  text ".VersionControl_RevNumber" at 1035.5,-656.17 h60
  text "SVN REV:" at 1541.5,-656.17 h60
  text ".PCB_Rev" at 2088,-656.17 h60
  text "REV:" at 2379.5,-656.17 h60
  text ".PRJ_Number" at 3224,-656.17 h60
  text "BOARD #:" at 3769.5,-656.17 h60
  text "PCB VIEWED FROM BOTTOM SIDE" at 6246,-656.17 h60
  text "IGNORE ->" at 2547.85,-858.49 h60
  text "TEXAS INSTRUMENTS" at 904.5,-1064.84 h60
  text ".Print_Time" at 2169,-1064.84 h60
  text ".Print_Date" at 2898,-1064.84 h60
  text "GENERATED    :" at 3767.5,-1064.84 h60
  text ".plot_File_Name" at 5440.5,-1064.84 h60
  text "PLOT NAME =" at 6246,-1064.84 h60
M9 Title Sheet:
  drawing of 57 lines, arcs and shapes, not listed
  text "1" at 739.84,8036.5 h70
  text "2" at 3235.5,8036.5 h70
  text "3" at 5724.84,8036.5 h70
  text "4" at 8231.51,8036.5 h70
  text "5" at 10730.5,8036.5 h70
  text "6" at 13235.5,8036.5 h70
  text "A" at -416.5,6893.5 h70
  text "A" at 14383.5,6893.5 h70
  text "B" at -416.5,4513.5 h70
  text "B" at 14383.5,4513.5 h70
  text "C" at -416.5,2138.5 h70
  text "C" at 14383.5,2138.5 h70
  text "PROJECT TITLE:" at 11343.5,277.5 h45
  text ".PRJ_Title" at 11393.5,144.17 h70
  text "DESIGNED FOR:" at 11343.5,-23.5 h45
  text ".PRJ_Customer" at 11393.5,-163.5 h70
  text "D" at -416.5,-231.5 h70
  text "D" at 14383.5,-231.5 h70
  text "FILE NAME:" at 11343.5,-323.5 h45
  text ".PCB_File_Name_No_Path" at 11393.5,-443.5 h70
  text "Texas Instruments (TI) and/or its licensors do not warrant the accuracy or completeness of this specification" at 6374,-605.34 h45
  text "ENGINEER:" at 11343.5,-613.5 h45
  text "LAYOUT BY:" at 12848.5,-613.5 h45
  text "or any information contained therein. TI and/or its licensors do not warrant that this design will meet" at 6329.01,-718 h45
  text ".PRJ_Engineer" at 11393.5,-768.49 h70
  text ".PCB_Layout" at 12899,-768.49 h70
  text "the specifications, will be suitable for your application or fit for any particular purpose, or will operate in" at 6329.01,-830.67 h45
  text ".Layer_Name" at 577,-858.49 h60
  text "ALTIUM DESIGNER VERSION:" at 12848.5,-923.5 h45
  text "an implementation. TI and/or its licensors do not warrant that the design is production worthy. You should" at 6329.01,-943.33 h45
  text "completely validate and test your design implementation to confirm the system functionality for your application." at 6374,-1056 h45
  text ".print_Scale" at 11393.5,-1056.83 h70
  text ".Application_BuildNumber" at 12899,-1056.83 h70
  text "1" at 739.84,-1263.5 h70
  text "2" at 3235.5,-1263.5 h70
  text "3" at 5724.84,-1263.5 h70
  text "4" at 8231.51,-1263.5 h70
  text "5" at 10730.5,-1263.5 h70
  text "6" at 13235.5,-1263.5 h70
M10 Fab Notes:
  drawing of 212 lines, arcs and shapes, not listed
  text "DESIGN INFORMATION" at 12381.02,6810 h60
  text "(REFER ALSO ARRAY/PANEL PROFILING INFORMATION)" at 12019.46,6648.29 h60
  text "BOARD SIZE" at 11333.46,6644 h60
  text "2300MIL" at 11795.78,6516.18 h60
  text "X" at 12301.46,6516.18 h60
  text "2845MIL" at 12532.78,6516.18 h60
  text "Number of Layers :" at 11736.46,6319 h60
  text "2" at 12831.27,6309 h60
  text "MIN. TRACK WIDTH:" at 11736.46,6180 h60
  text "8" at 12832.7,6180 h60
  text "MIL" at 12987.46,6180 h60
  text "MIN. CLEARANCE:" at 11736.46,6048 h60
  text "8" at 12832.7,6048 h60
  text "MIL" at 12987.46,6048 h60
  text "MIN. VIA PAD SIZE:" at 11736.46,5916 h60
  text "24" at 12802.71,5916 h60
  text "MIL" at 12987.46,5916 h60
  text "0.05mm (2MIL)" at 12431.46,5774.29 h60
  text "MINIMUM ANNULAR RING" at 11407.23,5770 h60
  text "EXTERNAL" at 13139.46,5770 h60
  text "PER" at 11607.23,5652 h60
  text "IPC-D-275 CLASS 2 LEVEL C" at 11827.23,5652 h60
  text "MIL, HOLES" at 13315.46,5539.71 h60
  text "+/-" at 12923,5539 h60
  text "+/-" at 13777,5539 h60
  text "REGISTRATION TOLERANCES:" at 11407.23,5534 h60
  text "METAL" at 12607,5534 h60
  text "5" at 13183.2,5534 h60
  text "3" at 14016.2,5534 h60
  text "MIL" at 14132.46,5534 h60
  text "MATERIAL:" at 11332.46,5324.54 h60
  text "FR-4 High Tg" at 12318.9,5184.21 h60
  text "X" at 13045,5180 h60
  text "FR-408" at 11753.46,5175.64 h60
  text "OTHER" at 13241.46,5175.64 h60
  text "FR4" at 13710,5175 h60
  text "62 MIL (1.6mm) +/-10%" at 12073.56,5012.92 h60
  text "THICKNESS:" at 11407.23,5008.64 h60
  text "X" at 11945.4,5008.64 h60
  text "OTHER" at 13358.46,5008.64 h60
  text "TOLERANCE:" at 11407.23,4850.64 h60
  text "X" at 12246.53,4850.64 h60
  text "ANSI IPC-6012 TYPE 3 CLASS 2" at 12433.48,4850.64 h60
  text "OTHER +/-" at 12433.46,4694.64 h60
  text "BOW & TWIST:" at 11407.23,4537.64 h60
  text "X" at 12246.53,4537.64 h60
  text "ANSI IPC-6012 TYPE 3 CLASS 2" at 12433.48,4537.64 h60
  text "OTHER +/-" at 12433.46,4379.13 h60
  text "COPPER THICKNESS (FINISHED):" at 11332.46,4243.64 h60
  text "1.4MIL (1oz)" at 12212.46,4090.92 h60
  text "2MIL (1.4oz)" at 12979.46,4090.92 h60
  text "2.8MIL (2oz)" at 13706.46,4090.92 h60
  text "OUTER:" at 11689.46,4086.64 h60
  text "X" at 12084,4086 h60
  text "0.7MIL (0.5oz)" at 12212.46,3933.92 h60
  text "2.8MIL (2oz)" at 12979.46,3933.92 h60
  text "N/A" at 13706,3934.29 h60
  text "INNER SIGNAL:" at 11400.38,3929.64 h60
  text "X" at 12085.42,3929.64 h60
  text "DRILLING:" at 11332.46,3790.64 h60
  text "REFERENCE:" at 11407.23,3673.64 h60
  text "X" at 12055.46,3673.64 h60
  text "AS SHOWN" at 12242.46,3673.64 h60
  text "X" at 12956.46,3673.64 h60
  text "NC_DRILL FILES" at 13093.46,3673.64 h60
  text "PTH MIN COPPER THICKNESS:" at 11407.23,3515.64 h60
  text "X" at 12757.46,3515.64 h60
  text "1MIL" at 12894.46,3515.64 h60
  text "OTHER" at 13391.46,3515.64 h60
  text "BOARD FINISH:" at 11332.46,3356.64 h60
  text "SILKSCREEN:" at 11487.68,3238.64 h60
  text "X" at 12436.46,3238.64 h60
  text "TOP" at 12562.46,3238.64 h60
  text "X" at 12946.46,3238.64 h60
  text "BOTTOM" at 13073.46,3238.64 h60
  text "SILKSCREEN COLOR:" at 11487.68,3071.64 h60
  text "X" at 12435.42,3071.64 h60
  text "WHITE" at 12562.46,3071.64 h60
  text "OTHER" at 13073.46,3071.64 h60
  text "SOLDER RESIST COLOR:" at 11487.68,2901.64 h60
  text "X" at 12055.42,2742.44 h60
  text "GREEN" at 12182.46,2742.44 h60
  text "BLUE" at 12773.46,2742.44 h60
  text "OTHER" at 13311.46,2742.44 h60
  text "IMMERSION GOLD (ENIG)" at 12393.46,2553.92 h60
  text "ENEPIG" at 13731,2550.64 h60
  text "SURFACE FINISH:" at 11332.46,2549.64 h60
  text "HASL" at 13500,2410 h60
  text "IMM. TIN/SILVER OR EQUIV" at 11662,2392.64 h60
  text "OTHER" at 13093.46,2392.64 h60
  text "X" at 12915,2390 h60
  text "X" at 12200,2215 h60
  text "ARRAY/PANEL:" at 11332.46,2213.64 h60
  text "CUT AND TRIM PER MECH LAYER 1" at 12393.46,2209.35 h60
  text "N.C. ROUTE" at 12393.46,2057.64 h60
  text "V. SCORE" at 13259.46,2057.64 h60
  text "CERTIFICATION:" at 11332.46,1920.64 h60
  text "MATERIALS AND WORKMANSHIP FOR ALL PCBS" at 12057.46,1920.64 h60
  text "TO MEET OR EXCEED THE REQUIREMENTS OF:" at 12057.46,1822.64 h60
  text "X" at 11683.96,1686.13 h60
  text "ANSI IPC-A-600F CLASS ->" at 11822.96,1686.13 h60
  text "X" at 13462.02,1686.13 h60
  text "2" at 13580.96,1686.14 h60
  text "1" at 13265.96,1684.64 h60
  text "3" at 13934.96,1684.64 h60
  text "X" at 11686.02,1526.64 h60
  text "UL 94V-0" at 11822.96,1526.64 h60
  text "X" at 12498.02,1526.64 h60
  text "RoHS" at 12634.96,1526.64 h60
  text "OTHER" at 13279.36,1526.64 h60
  text "PER ORDER" at 13676.42,1526.64 h60
  text "ADDITIONAL REQUIREMENTS:" at 11332.46,1385.64 h60
  text "MICROSECTION:" at 11407.23,1270.64 h60
  text "YES" at 12312.96,1270.64 h60
  text "REQUIRED" at 13174.46,1114.49 h60
  text "BARE BOARD ELEC. TEST:" at 11407.23,1111.64 h60
  text "NONE" at 12712.96,1111.64 h60
  text "X" at 13047.46,1111.64 h60
  text "PER ORDER" at 13766.46,1111.64 h60
  text "MANUFACTURER'S UL:" at 11407.23,954.64 h60
  text "RAIL" at 12572.96,950.35 h60
  text "METAL" at 13064.77,950.35 h60
  text "X" at 13440,950 h60
  text "SILK" at 13576.46,950.35 h60
  text ".Layer_Name" at 577,-858.49 h60
M11 Gerber Information:
  lines w10: -292,-930.17 6308,-930.17 ; -292,-726.83 6310,-726.83 ; -292,-523.5 -292,-1133.5 3713,-1133.5 6310,-1133.5 6310,-523.5 -291.5,-523.5 -291.5,-1133.5 1284,-1133.5 ; 2173,-1133.5 2173,-523.5 ; 3440,-726.83 3440,-523.5 ; 4280,-726.83 4280,-523.5 ; 4902,-1140 4902,-937.17
  text "ALL ARTWORK VIEWED FROM TOP SIDE" at -228.5,-655.67 h60
  text "BOARD #:" at 2248,-655.67 h60
  text ".PRJ_Number" at 2793.5,-655.67 h60
  text "REV:" at 3638,-655.67 h60
  text ".PCB_Rev" at 3929.5,-655.67 h60
  text "SVN REV:" at 4476,-655.67 h60
  text ".VersionControl_RevNumber" at 4982,-655.67 h60
  text "LAYER NAME =" at -228.5,-858.49 h60
  text "PLOT NAME =" at -228.5,-1064.34 h60
  text ".plot_File_Name" at 577,-1064.34 h60
  text "GENERATED    :" at 2250,-1064.34 h60
  text ".Print_Date" at 3119.5,-1064.34 h60
  text ".Print_Time" at 3848.5,-1064.34 h60
  text "TEXAS INSTRUMENTS" at 5113,-1064.34 h60
M12 Stackup:
  lines w16: 5900,6144.25 10695,6144.25 ; 5900,6430.85 10695,6430.85 ; 5840,4372 ccw(c5932,4372) 5932,4280 10663,4280 ccw(c10663,4372) 10755,4372 10755,6663 ccw(c10663,6663) 10663,6755 5932,6755 ccw(c5932,6663) 5840,6663 5840,4372
  text "Layer Stack Up Detail for: PMP10516.PcbDoc" at 5900,6511.32 h112
  text "Layer" at 5900,6323.85 h66
  text "Gerber" at 7621.83,6323.85 h66
  text "Copper" at 8456.34,6323.85 h66
  text "Dielectric" at 9398.62,6323.85 h66
  text "Name" at 5900,6191.85 h66
  text "Document" at 7621.83,6191.85 h66
  text "Thickness" at 8456.34,6191.85 h66
  text "Material" at 9398.62,6191.85 h66
  text "Top Solder Mask" at 5900,5998.23 h92
  text "(.GTS)" at 7621.83,5998.23 h92
  text "Solder Resist" at 9398.62,5998.23 h92
  text "Top Layer" at 5900,5722.19 h92
  text "(.GTL)" at 7621.83,5722.19 h92
  text "1.4mil" at 8456.34,5722.19 h92
  text "FR-4" at 9398.62,5584.17 h92
  text "MidLayer1" at 5900,5446.15 h92
  text "(.G1)" at 7621.83,5446.15 h92
  text "0.7mil" at 8456.34,5446.15 h92
  text "FR-4" at 9398.62,5308.13 h92
  text "MidLayer2" at 5900,5170.1 h92
  text "(.G2)" at 7621.83,5170.1 h92
  text "0.7mil" at 8456.34,5170.1 h92
  text "FR-4" at 9398.62,5032.08 h92
  text "Bottom Layer" at 5900,4894.06 h92
  text "(.GBL)" at 7621.83,4894.06 h92
  text "1.4mil" at 8456.34,4894.06 h92
  text "Bottom Solder Mask" at 5900,4618.02 h92
  text "(.GBS)" at 7621.83,4618.02 h92
  text "Solder Resist" at 9398.62,4618.02 h92
  text ".Layer_Name" at 577,-858.49 h60
M13 Component Bodies Top:
  text ".Layer_Name" at 577,-858.49 h60
M14 Component Bodies Bottom:
  text ".Layer_Name" at 577,-858.49 h60
M15 Courtyards Top:
  text ".Layer_Name" at 577,-858.49 h60
M16 Courtyards Bottom:
  text ".Layer_Name" at 577,-858.49 h60
Drill Drawing:
  text ".legend" at 2395,815 h60
  text "Drill Table" at 2395,615 h60
  text ".Layer_Name" at 577,-858.49 h60

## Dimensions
0,0 to 2300,0 on M2 Board Dimensions
0,0 to 0,2845 on M2 Board Dimensions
